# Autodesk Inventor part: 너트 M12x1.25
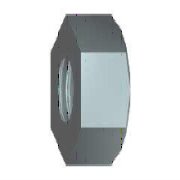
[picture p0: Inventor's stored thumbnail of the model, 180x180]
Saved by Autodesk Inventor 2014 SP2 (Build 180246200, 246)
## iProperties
IsCustomPart: 0
Created: 2015-12
Part Number: 너트 M12x1.25
Material: 스테인리스강
Description: 6각 너트
Document SubType Name: Modeling
Standard: KS B 1012
Designer: mdu
Standards Organization: KS
Language: ko-KR
Size Designation: M12x1.25
Categories: <MemberInstance><Categories><Category DisplayName="조임쇠" InternalName="e4da775c-781d-43d5-af7c-5136215cf5a6" Mnemonic="FSTN"><Category DisplayName="너트" InternalN
Density: 8.08 g/cm^3
Appearance: 반광택
Author: mdu
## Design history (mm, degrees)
sketch "스케치1"
  geometry: L1 (10.97, 0)-(5.485, -9.5); L2 (5.485, -9.5)-(-5.485, -9.5); L3 (-5.485, -9.5)-(-10.97, 0); L4 (-10.97, 0)-(-5.485, 9.5); L5 (-5.485, 9.5)-(5.485, 9.5); L6 (5.485, 9.5)-(10.97, 0); 2 further points
  constraints: 12 end point, 1 coincident, 1 horizontal, 11 other
  dimensions: "d0" = 21.93931 distance of L1.start L3.end (= 1.1547 x SW)
extrude "본체" new body sketch "스케치1" distance "d1" = 10 (= KOH); taper "d2" = 0 deg
sketch "스케치2"
  geometry: 1 further point
hole "스레드" sketch "스케치2" diameter "d6" = 10.647; stored, may be unused: countersink angle "d10" = 82 deg, drill point angle "d12" = 118 deg; dims "d7" = 12.7, "d8" = 9.525, "d9" = 6.35, "d11" = 19.05
sketch "스케치3"
  geometry: L1 (0, 10.97)-(10, 10.97) reference; L2 (10, 5.485)-(10, 10.97) reference; L3 (-2, 0)-(12, 0) reference; L4 (9.151, 10.97)-(10, 9.5)
  constraints: 2 end point, 2 point on line
  dimensions: "d3" = 19 diameter of L4.end L3 (= SW01); "d4" = 30 deg angle of L2 L4 (= ANG2)
revolve "모따기3" sketch "스케치3" stored, may be unused: angle "d5" = 90 deg
workaxis "Work Axis1"
workplane "Work Plane1"
body "Solid1"
chamfer "모따기1" distance "d13" = 0.67658 (= -0.5 x GD1 + 0.5 x NND); stored, may be unused: angle "d14" = 30 deg, second distance "d21" = 0.67658 (= -0.5 x GD1 + 0.5 x NND)
chamfer "모따기2" distance "d15" = 0.67658 (= -0.5 x GD1 + 0.5 x NND); stored, may be unused: angle "d16" = 30 deg, second distance "d22" = 0.67658 (= -0.5 x GD1 + 0.5 x NND)
other parameters: "ANG2" = 30 deg [user parameter; used in 1 equation term], "NND" = 12 [user parameter; used in 4 equation terms], "KOH" = 10 [user parameter; used in 1 equation term], "SW" = 19 [user parameter; used in 3 equation terms], "SW01" = 19 (= SW) [user parameter; used in 1 equation term], "GD1" = 10.64684 (computed from THREADDIA, PTC, TOA) [user parameter; used in 4 equation terms], "d19" = 0, "d20" = 0, "d24" = 0, "d25" = 0, "GUL" = 0.67658 (= 0.541266 x PTC) [user parameter], "TPU" = 8 (computed from PTC) [user parameter], "TOA" = 30 deg [user parameter; used in 1 equation term], "PTC" = 1.25 [user parameter; used in 4 equation terms], "E0" = 21.945 (= 1.155 x SW) [user parameter], "THREADDIA" = 12 [user parameter; used in 1 equation term], "GAL" = 0.67658 (= 0.541266 x PTC) [user parameter]
